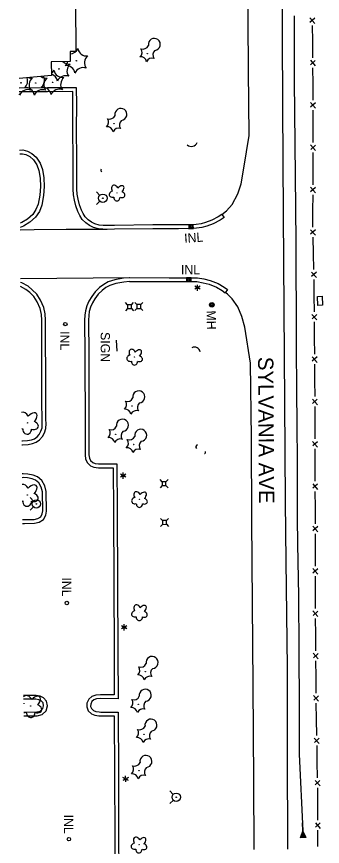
# Model space of a CAD drawing. Extents: x 588843 to 2552415, y 180129 to 269402.
# Drawn here: x 593747 to 593947, y 181177 to 181719 of the extents above; entities that cross this region are included whole.
import ezdxf

# ---------------------------------------------------------------- set-up
doc = ezdxf.new("R2010")
doc.units = 0
for name, color, linetype in [('Default', 7, 'Continuous'), ('E_BLD', 7, 'Continuous'), ('E_BMGRD', 7, 'Continuous'), ('E_DRN', 7, 'Continuous'), ('E_DRN_Text', 7, 'Continuous'), ('E_DWY', 7, 'Continuous'), ('E_FEN_P', 7, 'Continuous'), ('E_LAND_Vegetation', 7, 'Continuous'), ('E_LTG', 7, 'Continuous'), ('E_RDWY', 7, 'Continuous'), ('E_RDWY_C_and_G', 7, 'Continuous'), ('E_RDWY_Text', 7, 'Continuous'), ('E_SGN', 7, 'Continuous'), ('E_SGN_Text', 7, 'Continuous'), ('E_UTL_AG_Bold', 7, 'Continuous'), ('E_UTL_MH', 7, 'Continuous'), ('E_UTL_MH_Text', 7, 'Continuous'), ('E_UTL_WHydrant', 7, 'Continuous'), ('P_BMGRD', 7, 'Continuous')]:
    doc.layers.add(name, color=color, linetype=linetype)

# ---------------------------------------------------------------- blocks, each defined once
blk = doc.blocks.new('CULV2')
at = {"layer": 'E_DRN'}
blk.add_arc((19.7, 14.8), 24.6, 216.8699, 323.1301, dxfattribs=at)
blk = doc.blocks.new('INLO')
at = {"layer": 'E_DRN'}
for p, q in [((2, -4), (2, 0)), ((4, -4), (4, 0)), ((6, -2), (0, -2))]:
    blk.add_line(p, q, dxfattribs=at)
blk.add_lwpolyline([(0, -4), (6, -4), (6, 0), (0, 0), (0, -4)], close=True, dxfattribs=at)
blk = doc.blocks.new('INLT_5')
at = {"layer": 'E_DRN_Text'}
blk.add_text('INL', height=12, dxfattribs=at).set_placement((-11, -6))
blk = doc.blocks.new('INLT_6')
at = {"layer": 'E_DRN_Text'}
blk.add_text('INL', height=12, dxfattribs=at).set_placement((-11, -6))
blk = doc.blocks.new('MHO')
at = {"layer": 'Default'}
for centre, radius in [((0.1, -0.1), 3), ((0.1, -0.1), 2.43), ((0.1, -0.1), 1.94), ((0, -0.2), 1.21)]:
    blk.add_circle(centre, radius, dxfattribs=at)
blk = doc.blocks.new('MHT')
at = {"layer": 'E_UTL_MH_Text'}
blk.add_text('MH', height=12, dxfattribs=at).set_placement((-9.8, -6))
blk = doc.blocks.new('HYD')
at = {"layer": 'Default'}
for p, q in [((-3.8, 3.8), (-8.3, 8.3)), ((3.8, 3.8), (8.3, 8.3))]:
    blk.add_line(p, q, dxfattribs=at)
for radius in [5.48, 0.42]:
    blk.add_circle((0, 0), radius, dxfattribs=at)
blk = doc.blocks.new('PED')
at = {"layer": 'Default'}
for p, q in [((-2.5, 2.5), (-5.3, 5.3)), ((2.5, 2.5), (5.3, 5.3)), ((-2.5, -2.5), (-5.3, -5.3)), ((2.5, -2.5), (5.3, -5.3))]:
    blk.add_line(p, q, dxfattribs=at)
blk.add_lwpolyline([(-2.5, -2.5), (2.5, -2.5), (2.5, 2.5), (-2.5, 2.5)], close=True, dxfattribs=at)
blk = doc.blocks.new('LPOL')
at = {"layer": 'Default'}
for p, q in [((-4, 0), (-1.5, 0)), ((-0.7, 1.3), (-2, 3.5)), ((0.7, 1.3), (2, 3.5)), ((1.5, 0), (4, 0)), ((-2, -3.5), (-0.7, -1.3)), ((2, -3.5), (0.7, -1.3))]:
    blk.add_line(p, q, dxfattribs=at)
for radius in [1.5, 1.5, 1.5, 0.125]:
    blk.add_circle((0, 0), radius, dxfattribs=at)
blk = doc.blocks.new('CTRE')
at = {"layer": 'Default'}
blk.add_circle((0, 0), 0.223, dxfattribs=at)
for centre, start, end in [((-12, 9), 280.2067, 5.9716), ((-13.8, -5.9), 340.2113, 65.9762), ((1.8, 14.9), 220.2113, 305.9762), ((13.8, 5.9), 160.2113, 245.9762), ((-1.8, -14.9), 40.2113, 125.9762), ((12, -9), 185.9272, 100.2511)]:
    blk.add_arc(centre, 7.87, start, end, dxfattribs=at)
blk = doc.blocks.new('DTRE')
at = {"layer": 'Default'}
blk.add_circle((-0.2, 0), 0.183, dxfattribs=at)
for centre, major_axis, ratio in [((-1.9, 5.3), (1.36, -4.98), 0.782863), ((-5.9, 0.2), (4.93, -0.12), 0.832022), ((4.1, 2.7), (-5.27, -2.93), 0.691916), ((-2.5, -5.2), (1.8, 4.86), 0.716896), ((3.5, -3.7), (-5.01, 4.58), 0.560249)]:
    blk.add_ellipse(centre, major_axis=major_axis, ratio=ratio, start_param=1.570796, end_param=4.712389, dxfattribs=at)
blk = doc.blocks.new('INLT_4')
at = {"layer": 'E_DRN_Text'}
blk.add_text('INL', height=12, dxfattribs=at).set_placement((-11, -6))
blk = doc.blocks.new('SIGN')
at = {"layer": 'Default'}
blk.add_text('SIGN', height=12, dxfattribs=at).set_placement((-18.5, -6))

msp = doc.modelspace()

# ---------------------------------------------------------------- linework, layer by layer
at = {"layer": 'E_BLD'}
msp.add_lwpolyline([(593746.54, 181885.28), (593783.92, 181885.57), (593785.4, 181695.78), (593781.62, 181695.75), (593781.67, 181689.27), (593769.25, 181689.17), (593769.32, 181680.04), (593748.22, 181678.18)], dxfattribs=at)
at = {"layer": 'E_BMGRD'}
for p, q in [((593933.85, 181186.87), (593933.6, 181192.14)), ((593933.85, 181186.87), (593932.09, 181182.28)), ((593934.82, 181184.91), (593933.07, 181184.83)), ((593934.58, 181185.4), (593933.27, 181185.34)), ((593934.34, 181185.89), (593933.46, 181185.85)), ((593934.09, 181186.38), (593933.66, 181186.36)), ((593936.04, 181182.47), (593933.85, 181186.87)), ((593936.04, 181182.47), (593932.09, 181182.28)), ((593935.8, 181182.96), (593932.29, 181182.79)), ((593935.55, 181183.45), (593932.48, 181183.3)), ((593935.31, 181183.94), (593932.68, 181183.81)), ((593935.07, 181184.43), (593932.87, 181184.32))]:
    msp.add_line(p, q, dxfattribs=at)
at = {"layer": 'E_DRN'}
msp.add_lwpolyline([(593943.62, 181529.99), (593943.45, 181535.92), (593946.46, 181536.01), (593946.63, 181530.07), (593943.62, 181529.99)], close=True, dxfattribs=at)
for centre, radius in [((593778.43, 181517.81), 1.13), ((593779.43, 181335.68), 1.1), ((593780.79, 181181.44), 1.1)]:
    msp.add_circle(centre, radius, dxfattribs=at)
at = {"layer": 'E_DWY'}
for points in [[(593805.84, 181582.12), (593803.16, 181582.19), (593800.63, 181582.46), (593797.75, 181583.3), (593795.6, 181584.35), (593793.42, 181585.87), (593791.5, 181587.78), (593790.05, 181589.94), (593788.94, 181592.27), (593787.68, 181595.77), (593786.8, 181599.3), (593786.22, 181602.54), (593786.07, 181605.89), (593786.06, 181609.9), (593785.99, 181625.48), (593785.83, 181645.19), (593785.9, 181661.51), (593785.81, 181672.18), (593766.87, 181672.06), (593748.26, 181671.97)], [(593805.78, 181579.62), (593803, 181579.69), (593800.14, 181580), (593796.84, 181580.96), (593794.33, 181582.19), (593791.81, 181583.94), (593789.56, 181586.18), (593787.87, 181588.7), (593786.63, 181591.31), (593785.28, 181595.04), (593784.35, 181598.78), (593783.73, 181602.26), (593783.57, 181605.83), (593783.56, 181609.89), (593783.49, 181625.46), (593783.33, 181645.19), (593783.4, 181661.5), (593783.33, 181669.66), (593766.88, 181669.56), (593748.28, 181669.47)], [(593748.56, 181631.4), (593750.61, 181631.59), (593753.61, 181630.8), (593756.6, 181629.27), (593759.43, 181626.73), (593761.95, 181622.99), (593763.51, 181618.82), (593764.46, 181613.36), (593764.64, 181607.57), (593764.26, 181601.77), (593763.13, 181595.52), (593761.46, 181591.4), (593759.02, 181587.71), (593755.26, 181584.35), (593751.14, 181581.83), (593748.93, 181580.98)], [(593748.58, 181628.89), (593750.4, 181629.06), (593752.71, 181628.45), (593755.18, 181627.19), (593757.53, 181625.08), (593759.71, 181621.83), (593761.09, 181618.17), (593761.96, 181613.1), (593762.14, 181607.61), (593761.78, 181602.07), (593760.71, 181596.22), (593759.24, 181592.57), (593757.12, 181589.36), (593753.76, 181586.37), (593750.03, 181584.08), (593748.91, 181583.65)], [(593820.24, 181548.12), (593816.42, 181547.76), (593810.93, 181546.72), (593806.56, 181545.34), (593803.63, 181543.72), (593800.85, 181541.75), (593798.03, 181538.91), (593795.67, 181535.78), (593793.91, 181532.83), (593792.45, 181529.78), (593791.57, 181526.42), (593791.25, 181523.71), (593791.06, 181520.44), (593791.08, 181515.51), (593791.21, 181503.19), (593791.3, 181486.14), (593791.4, 181461.13), (593791.38, 181443.54)], [(593749.97, 181439.01), (593750.5, 181438.99), (593754.03, 181439.19), (593756.9, 181439.73), (593759.39, 181440.69), (593761.57, 181442.19), (593763.52, 181444.37), (593764.76, 181446.82), (593765.67, 181449.58), (593765.85, 181452.96), (593765.79, 181455.6), (593765.66, 181466.85), (593765.63, 181485.41), (593765.51, 181507.25), (593765.55, 181520.39), (593765.29, 181524.42), (593764.43, 181528.68), (593762.27, 181533.49), (593759.73, 181537.32), (593756.85, 181540.25), (593754.11, 181542.48), (593749.99, 181544.76), (593749.19, 181545.05)], [(593749.95, 181441.52), (593750.49, 181441.49), (593753.73, 181441.68), (593756.21, 181442.14), (593758.21, 181442.92), (593759.91, 181444.08), (593761.43, 181445.79), (593762.45, 181447.78), (593763.19, 181450.05), (593763.35, 181453.01), (593763.29, 181455.56), (593763.16, 181466.84), (593763.13, 181485.4), (593763.01, 181507.24), (593763.05, 181520.32), (593762.81, 181524.08), (593762.03, 181527.91), (593760.07, 181532.28), (593757.78, 181535.74), (593755.16, 181538.4), (593752.7, 181540.4), (593749.21, 181542.33)], [(593820.48, 181545.63), (593816.77, 181545.28), (593811.54, 181544.29), (593807.55, 181543.03), (593804.96, 181541.59), (593802.47, 181539.84), (593799.92, 181537.27), (593797.75, 181534.38), (593796.12, 181531.65), (593794.81, 181528.92), (593794.03, 181525.96), (593793.75, 181523.49), (593793.56, 181520.37), (593793.58, 181515.53), (593793.71, 181503.21), (593793.8, 181486.15), (593793.9, 181461.13), (593793.88, 181443.54)], [(593791.38, 181443.53), (593791.41, 181432.36), (593791.73, 181429.55), (593792.99, 181427.14), (593794.93, 181425.34), (593797.15, 181424.29), (593800.07, 181423.94), (593809.63, 181423.95), (593809.87, 181395.56), (593810.13, 181348.75), (593810.35, 181303.24), (593810.45, 181275.65), (593801.42, 181275.75), (593798.4, 181275.52), (593795.87, 181274.65), (593793.71, 181272.96), (593792.59, 181270.17), (593792.49, 181267.77), (593793.31, 181265.33), (593795.47, 181263.32), (593797.75, 181262.46), (593800.28, 181261.99), (593801.64, 181261.98), (593810.47, 181261.96), (593810.71, 181224.62)], [(593793.88, 181443.54), (593793.91, 181432.51), (593794.16, 181430.3), (593795.01, 181428.68), (593796.35, 181427.43), (593797.85, 181426.72), (593800.21, 181426.44), (593812.11, 181426.46), (593812.37, 181395.58), (593812.63, 181348.76), (593812.85, 181303.25), (593812.96, 181273.12), (593801.5, 181273.25), (593798.91, 181273.05), (593797.08, 181272.42), (593795.78, 181271.41), (593795.07, 181269.64), (593795.01, 181268.13), (593795.48, 181266.73), (593796.82, 181265.48), (593798.43, 181264.88), (593800.52, 181264.49), (593801.65, 181264.48), (593812.95, 181264.45), (593813.21, 181224.64)], [(593750.34, 181387.63), (593751.78, 181387.63), (593758.34, 181387.75), (593761.41, 181388.42), (593764.19, 181390.11), (593765.74, 181392.99), (593766.19, 181395.56), (593765.94, 181408.52), (593765, 181412.21), (593762.96, 181415.69), (593760.24, 181418.02), (593757.45, 181419.14), (593754, 181419.83), (593750.9, 181420.04), (593750.1, 181419.93)], [(593750.32, 181390.13), (593751.75, 181390.13), (593758.05, 181390.25), (593760.47, 181390.77), (593762.31, 181391.89), (593763.35, 181393.82), (593763.68, 181395.75), (593763.45, 181408.18), (593762.66, 181411.25), (593761.02, 181414.06), (593758.93, 181415.85), (593756.73, 181416.73), (593753.67, 181417.34), (593750.98, 181417.52), (593750.12, 181417.41)], [(593751.26, 181261.96), (593760.07, 181262), (593763.38, 181262.88), (593765.98, 181265.36), (593766.8, 181268.55), (593766.18, 181271.59), (593764.1, 181273.79), (593761.95, 181274.84), (593759.39, 181275.35), (593751.16, 181275.27)], [(593751.24, 181264.46), (593759.74, 181264.5), (593762.11, 181265.13), (593763.74, 181266.68), (593764.24, 181268.61), (593763.87, 181270.39), (593762.59, 181271.74), (593761.14, 181272.45), (593759.16, 181272.84), (593751.18, 181272.77)], [(593810.71, 181224.63), (593810.79, 181182.72), (593810.87, 181161.35)], [(593813.21, 181224.64), (593813.29, 181182.72), (593813.37, 181161.36)]]:
    msp.add_lwpolyline(points, dxfattribs=at)
at = {"layer": 'E_FEN_P'}
for p, q in [((593938.38, 181717.78), (593941.64, 181714.15)), ((593941.59, 181717.66), (593938.49, 181714.85)), ((593938.74, 181690.14), (593941.96, 181686.47)), ((593941.95, 181689.98), (593938.82, 181687.2)), ((593938.83, 181662.47), (593942.04, 181658.8)), ((593942.03, 181662.31), (593938.9, 181659.54)), ((593938.91, 181634.81), (593942.13, 181631.14)), ((593942.12, 181634.65), (593938.99, 181631.87)), ((593938.82, 181607.15), (593942, 181603.46)), ((593942.02, 181606.97), (593938.87, 181604.22)), ((593938.79, 181579.45), (593942.08, 181575.85)), ((593942, 181579.36), (593938.93, 181576.51)), ((593939.44, 181551.81), (593942.68, 181548.16)), ((593942.65, 181551.68), (593939.54, 181548.88)), ((593939.71, 181524.15), (593942.96, 181520.5)), ((593942.92, 181524.01), (593939.81, 181521.21)), ((593939.91, 181496.49), (593943.13, 181492.83)), ((593943.11, 181496.34), (593939.99, 181493.55)), ((593940.08, 181468.82), (593943.31, 181465.17)), ((593943.29, 181468.68), (593940.17, 181465.89)), ((593940.2, 181441.17), (593943.41, 181437.49)), ((593943.41, 181441), (593940.27, 181438.23)), ((593940.26, 181413.5), (593943.47, 181409.83)), ((593943.47, 181413.34), (593940.34, 181410.56)), ((593940.32, 181385.84), (593943.53, 181382.16)), ((593943.52, 181385.67), (593940.39, 181382.9)), ((593940.36, 181358.17), (593943.57, 181354.5)), ((593943.56, 181358.01), (593940.43, 181355.24)), ((593940.39, 181330.5), (593943.62, 181326.84)), ((593943.6, 181330.35), (593940.48, 181327.56)), ((593940.61, 181302.83), (593943.84, 181299.18)), ((593943.81, 181302.69), (593940.7, 181299.9)), ((593940.82, 181275.17), (593944.06, 181271.52)), ((593944.03, 181275.03), (593940.91, 181272.23)), ((593941.29, 181247.49), (593944.56, 181243.87)), ((593944.5, 181247.38), (593941.41, 181244.56)), ((593941.79, 181219.83), (593945.07, 181216.21)), ((593945, 181219.72), (593941.91, 181216.9)), ((593941.99, 181192.2), (593945.19, 181188.52)), ((593945.19, 181192.03), (593942.05, 181189.26))]:
    msp.add_line(p, q, dxfattribs=at)
for points in [[(593939.93, 181712.89), (593940.09, 181702.33)], [(593940.09, 181702.33), (593940.21, 181694.03), (593940.22, 181691.77)], [(593940.24, 181685.23), (593940.27, 181674.67)], [(593940.27, 181674.67), (593940.3, 181664.1)], [(593940.32, 181657.56), (593940.36, 181647)], [(593940.36, 181647), (593940.39, 181636.44)], [(593940.4, 181629.9), (593940.35, 181619.34)], [(593940.35, 181619.34), (593940.3, 181608.77)], [(593940.27, 181602.23), (593940.22, 181591.67)], [(593940.22, 181591.67), (593940.18, 181583.36), (593940.23, 181581.11)], [(593940.39, 181574.57), (593940.63, 181564.01)], [(593940.63, 181564.01), (593940.88, 181553.45)], [(593940.97, 181546.91), (593941.07, 181536.35)], [(593941.07, 181536.35), (593941.18, 181525.79)], [(593941.24, 181519.25), (593941.31, 181508.69)], [(593941.31, 181508.69), (593941.38, 181498.12)], [(593941.42, 181491.58), (593941.49, 181481.02)], [(593941.49, 181481.02), (593941.55, 181470.46)], [(593941.6, 181463.92), (593941.65, 181455.84), (593941.65, 181453.36)], [(593941.65, 181453.36), (593941.68, 181442.79)], [(593941.69, 181436.26), (593941.71, 181425.69)], [(593941.71, 181425.69), (593941.74, 181415.13)], [(593941.75, 181408.59), (593941.78, 181398.03)], [(593941.78, 181398.03), (593941.79, 181392.29), (593941.8, 181387.46)], [(593941.81, 181380.93), (593941.82, 181370.36)], [(593941.82, 181370.36), (593941.84, 181359.8)], [(593941.85, 181353.26), (593941.86, 181342.7)], [(593941.86, 181342.7), (593941.88, 181332.14)], [(593941.91, 181325.6), (593941.99, 181315.03)], [(593941.99, 181315.03), (593942.07, 181304.47)], [(593942.13, 181297.93), (593942.21, 181287.37)], [(593942.21, 181287.37), (593942.29, 181276.81)], [(593942.35, 181270.27), (593942.55, 181259.71)], [(593942.55, 181259.71), (593942.74, 181249.15)], [(593942.86, 181242.61), (593943.05, 181232.05)], [(593943.05, 181232.05), (593943.24, 181221.49)], [(593943.36, 181214.95), (593943.5, 181207.68), (593943.49, 181204.39)], [(593943.49, 181204.39), (593943.47, 181193.82)], [(593943.46, 181187.28), (593943.44, 181176.72)]]:
    msp.add_lwpolyline(points, dxfattribs=at)
at = {"layer": 'E_LAND_Vegetation'}
for centre, radius in [((593785.67, 181689.74), 0.167), ((593774.23, 181684.44), 0.167), ((593749.41, 181675.36), 0.167), ((593759.1, 181675.29), 0.167), ((593770.08, 181675.65), 0.167), ((593753.59, 181453.34), 0.128), ((593753.57, 181406.24), 0.128), ((593755.85, 181268.32), 0.128)]:
    msp.add_circle(centre, radius, dxfattribs=at)
for centre, radius, start, end in [((593781.23, 181700.11), 5.9, 273.8501, 336.0597), ((593792.43, 181698.77), 5.91, 190.3346, 276.0107), ((593780.99, 181693.47), 5.91, 225.9273, 276.0107), ((593774.48, 181691.08), 5.9, 310.2948, 341.9988), ((593796.87, 181688.4), 5.9, 130.2948, 216.0597), ((593765.64, 181686.01), 5.9, 308.5194, 336.0597), ((593776.84, 181684.68), 5.91, 190.3346, 276.0107), ((593778.96, 181680.75), 5.9, 10.2901, 96.0551), ((593785.42, 181683.1), 5.9, 130.2948, 216.0597), ((593790.11, 181679.37), 5.9, 70.2948, 156.0597), ((593747.9, 181676.63), 5.9, 310.2948, 19.882), ((593756.18, 181684.39), 5.91, 253.5294, 276.0107), ((593760.61, 181674.02), 5.9, 130.2948, 216.0597), ((593765.86, 181684.33), 5.91, 235.7931, 276.0107), ((593758.88, 181676.98), 5.9, 310.2948, 26.169), ((593770.29, 181673.95), 5.9, 130.2948, 216.0597), ((593767.52, 181675.45), 5.9, 10.2901, 72.2559), ((593778.66, 181674.07), 5.9, 70.2948, 156.0597), ((593781.27, 181674.31), 5.9, 130.2948, 216.0597), ((593763.37, 181666.66), 5.9, 10.2901, 96.0551), ((593742.7, 181666.37), 5.9, 10.2901, 18.7299), ((593753.85, 181665), 5.9, 70.2948, 156.0597), ((593752.39, 181666.3), 5.9, 10.2901, 96.0551), ((593763.53, 181664.93), 5.9, 70.2948, 156.0597), ((593774.51, 181665.28), 5.9, 70.2948, 156.0597)]:
    msp.add_arc(centre, radius, start, end, dxfattribs=at)
for centre, major_axis, ratio, start_param, end_param in [((593751.67, 181456.31), (2.06, -3.69), 0.691916, 1.570796, 3.067827), ((593756.18, 181455.96), (-3.2, -3.51), 0.560249, 1.570796, 4.712389), ((593757.27, 181451.73), (-3.4, 1.26), 0.716896, 1.570796, 4.712389), ((593749.87, 181452.16), (3.49, 0.96), 0.782863, 4.506299, 4.712389), ((593753.49, 181449.36), (0.08, 3.45), 0.832022, 1.570796, 4.712389), ((593751.65, 181409.2), (2.06, -3.69), 0.691916, 1.570796, 2.937369), ((593756.16, 181408.85), (-3.2, -3.51), 0.560249, 1.570796, 4.712389), ((593757.24, 181404.63), (-3.4, 1.26), 0.716896, 1.570796, 4.712389), ((593749.85, 181405.05), (3.49, 0.96), 0.782863, 4.609461, 4.712389), ((593753.47, 181402.26), (0.08, 3.45), 0.832022, 1.570796, 4.712389), ((593753.93, 181271.28), (2.06, -3.69), 0.691916, 1.570796, 3.465073), ((593758.44, 181270.93), (-3.2, -3.51), 0.560249, 1.570796, 4.712389), ((593753.93, 181271.28), (2.06, -3.69), 0.691916, 4.620322, 4.712389), ((593752.13, 181267.13), (3.49, 0.96), 0.782863, 1.570796, 1.621375), ((593759.52, 181266.7), (-3.4, 1.26), 0.716896, 1.570796, 4.712389), ((593752.13, 181267.13), (3.49, 0.96), 0.782863, 4.250261, 4.712389), ((593755.75, 181264.33), (0.08, 3.45), 0.832022, 1.570796, 4.712389)]:
    msp.add_ellipse(centre, major_axis=major_axis, ratio=ratio, start_param=start_param, end_param=end_param, dxfattribs=at)
at = {"layer": 'E_RDWY'}
for points in [[(593898.68, 181640.91), (593898.23, 181683.47), (593897.83, 181748.36)], [(593920.04, 181747.12), (593920.2, 181707.24), (593920.49, 181659.97), (593920.92, 181589.62), (593921.33, 181527.56), (593921.83, 181466.82), (593922.3, 181401.73), (593922.65, 181362.99), (593923.47, 181293.57), (593923.63, 181239.18), (593923.73, 181174.95)], [(593880.92, 181589.37), (593883.95, 181591.73), (593887.53, 181595.96), (593891.29, 181602.82), (593893.54, 181609.37), (593895.23, 181619.52), (593898.68, 181640.91)], [(593805.89, 181579.62), (593778.89, 181579.52), (593758.09, 181579.28), (593748.94, 181579.14)], [(593899.68, 181492.3), (593895.84, 181515.79), (593893.95, 181522.69), (593891.25, 181529), (593887.68, 181534.19), (593884.58, 181537.33), (593883.03, 181538.39)], [(593901.88, 181174.73), (593901.67, 181219.23), (593901.26, 181282.13), (593900.88, 181335.13), (593900.51, 181390.23), (593900.19, 181443.49), (593899.68, 181492.3)]]:
    msp.add_lwpolyline(points, dxfattribs=at)
at = {"layer": 'E_RDWY_C_and_G'}
for points in [[(593880.86, 181589.45), (593878.5, 181587.78), (593874.18, 181585.6), (593870.24, 181584.12), (593867.22, 181583.28), (593864.05, 181582.93), (593859.53, 181582.64), (593852.53, 181582.58), (593835.69, 181582.54), (593810.67, 181582.23), (593805.84, 181582.12)], [(593880.86, 181589.45), (593882.31, 181587.41), (593879.79, 181585.63), (593875.19, 181583.31), (593871.02, 181581.74), (593867.7, 181580.82), (593864.27, 181580.44), (593859.62, 181580.14), (593852.55, 181580.08), (593835.71, 181580.04), (593810.71, 181579.73), (593805.89, 181579.62)], [(593749.17, 181547.62), (593820.46, 181548.13)], [(593820.48, 181548.13), (593846.32, 181548.12), (593860.77, 181548.12), (593864.81, 181548.04), (593869.12, 181547.26), (593873.27, 181546.21), (593878.33, 181544.27), (593882.32, 181541.92), (593884.46, 181540.31), (593882.97, 181538.31)], [(593820.48, 181545.63), (593846.32, 181545.62), (593860.74, 181545.62), (593864.56, 181545.54), (593868.59, 181544.81), (593872.51, 181543.82), (593877.24, 181542.01), (593880.93, 181539.83), (593882.97, 181538.31)]]:
    msp.add_lwpolyline(points, dxfattribs=at)
at = {"layer": 'E_SGN'}
msp.add_line((593812.32, 181500.21), (593811.83, 181507.27), dxfattribs=at)
at = {"layer": 'P_BMGRD'}
for p, q in [((593929.24, 181551.27), (593929.34, 181527.91)), ((593929.34, 181528), (593929.5, 181517.13))]:
    msp.add_line(p, q, dxfattribs=at)
for points in [[(593928.11, 181719.16), (593928.07, 181699.72), (593928.24, 181676.29), (593928.37, 181656.5), (593928.84, 181614.37), (593928.98, 181593.77), (593929.16, 181570.94), (593929.24, 181551.27)], [(593929.5, 181517), (593929.49, 181504.51), (593929.5, 181502.02), (593929.61, 181475.14), (593929.87, 181451.37), (593930.11, 181428.7), (593930.15, 181391.04), (593930.36, 181374.36), (593930.91, 181340.13), (593931.24, 181305.37), (593931.39, 181267.18), (593931.48, 181236.87), (593933.85, 181186.87)]]:
    msp.add_lwpolyline(points, dxfattribs=at)

# ---------------------------------------------------------------- block references
at = {"layer": 'E_DRN'}
for name, p, xscale, yscale, rotation in [('CULV2', (593858.17, 181634.76), 0.16906879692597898, 0.16906879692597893, 13.630832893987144), ('CULV2', (593801.86, 181618.9), 0.04243813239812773, 0.04243813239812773, -75.47399340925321), ('INLO', (593862.26, 181580.31), 0.5, 0.5, -176.32091039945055), ('CULV2', (593866.69, 181499.66), 0.1552672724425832, 0.1552672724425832, 153.48067681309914), ('CULV2', (593864.8, 181438.93), 0.0623375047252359, 0.062337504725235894, -105.66052929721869), ('CULV2', (593869.39, 181433.25), 0.03797750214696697, 0.03797750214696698, 59.33815225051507)]:
    msp.add_blockref(name, p, dxfattribs=dict(at, xscale=xscale, yscale=yscale, rotation=rotation))
at = {"layer": 'E_DRN', "xscale": 0.5, "yscale": 0.5}
msp.add_blockref('INLO', (593857.78, 181548.12), dxfattribs=at)
at = {"layer": 'E_DRN_Text'}
for name, p, xscale, yscale, rotation in [('INLT_6', (593861.68, 181574.2), 0.49999999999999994, 0.49999999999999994, 3.6790896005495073), ('INLT_4', (593778.1, 181507.67), 0.5, 0.5, -89.91655059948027), ('INLT_4', (593779.33, 181346.89), 0.5, 0.5, -89.91655059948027), ('INLT_4', (593780.6, 181191.93), 0.5, 0.5, -89.91655059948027)]:
    msp.add_blockref(name, p, dxfattribs=dict(at, xscale=xscale, yscale=yscale, rotation=rotation))
at = {"layer": 'E_DRN_Text', "xscale": 0.5, "yscale": 0.5}
msp.add_blockref('INLT_5', (593859.6, 181553.35), dxfattribs=at)
at = {"layer": 'E_LAND_Vegetation', "xscale": 0.5000000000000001, "yscale": 0.5, "rotation": 90.08344940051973}
for name, p in [('CTRE', (593832.16, 181694.45)), ('CTRE', (593810.3, 181648.74)), ('DTRE', (593812.31, 181603.63)), ('DTRE', (593823.79, 181496.48)), ('CTRE', (593822.01, 181464.26)), ('CTRE', (593811.34, 181445.74)), ('CTRE', (593823.23, 181439.15)), ('DTRE', (593827, 181403.49)), ('DTRE', (593826.95, 181329.57)), ('CTRE', (593830.7, 181290.81)), ('CTRE', (593826.21, 181269.46)), ('CTRE', (593829.95, 181249.91)), ('CTRE', (593826.68, 181226.22)), ('DTRE', (593826.65, 181177.88))]:
    msp.add_blockref(name, p, dxfattribs=at)
at = {"layer": 'E_LTG', "xscale": 0.5000000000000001, "yscale": 0.5, "rotation": 90.08344940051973}
for p in [(593864.89, 181541.53), (593816.3, 181418.83), (593817, 181319.82), (593817.91, 181220.82)]:
    msp.add_blockref('LPOL', p, dxfattribs=at)
at = {"layer": 'E_SGN_Text', "xscale": 0.5, "yscale": 0.5, "rotation": -89.91655059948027}
msp.add_blockref('SIGN', (593804.6, 181503.34), dxfattribs=at)
at = {"layer": 'E_UTL_AG_Bold', "xscale": 0.5000000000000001, "yscale": 0.5, "rotation": 90.08344940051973}
for p in [(593820.39, 181529.2), (593826.52, 181529.26), (593843.03, 181413.58), (593843.28, 181388.29)]:
    msp.add_blockref('PED', p, dxfattribs=at)
at = {"layer": 'E_UTL_MH', "xscale": 0.5, "yscale": 0.5, "rotation": 91.23181393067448}
msp.add_blockref('MHO', (593874.2, 181530.33), dxfattribs=at)
at = {"layer": 'E_UTL_MH_Text', "xscale": 0.5, "yscale": 0.5000000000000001, "rotation": -88.76818606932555}
msp.add_blockref('MHT', (593873.93, 181521.78), dxfattribs=at)
at = {"layer": 'E_UTL_WHydrant', "xscale": 0.5000000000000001, "yscale": 0.5, "rotation": 90.08344940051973}
for p in [(593802.96, 181599.96), (593759.49, 181400.38), (593850.99, 181208.8)]:
    msp.add_blockref('HYD', p, dxfattribs=at)

# ---------------------------------------------------------------- texts
at = {"layer": 'E_RDWY_Text'}
msp.add_text('SYLVANIA AVE', height=10, rotation=270.3661, dxfattribs=at).set_placement((593904.5, 181496.41))

doc.saveas('drawing.dxf')
